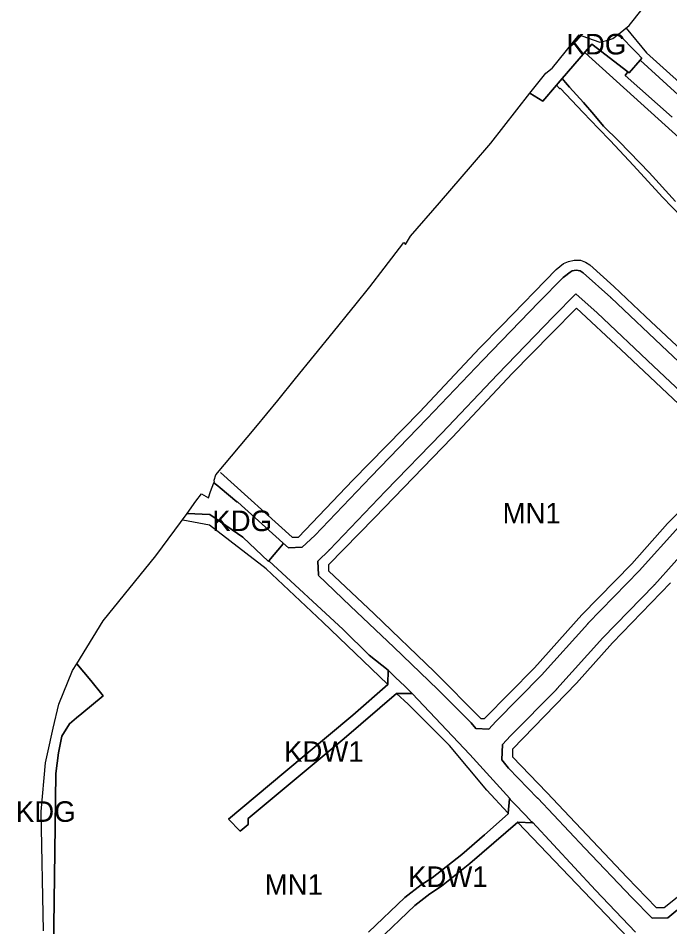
# Model space of a CAD drawing. Extents: x -284239 to -281592, y 34477 to 37267.
# Drawn here: x -284177.6 to -283861.3, y 35288.9 to 35729.6 of the extents above; entities that cross this region are included whole.
import ezdxf

# ---------------------------------------------------------------- set-up
doc = ezdxf.new("R2010")
doc.units = 0
for name, color, linetype in [('linie_rozgraniczajace', 7, 'Continuous'), ('linie_zabudowy_nieprzekraczalne', 7, 'Continuous'), ('oznaczenia_przeznaczen', 7, 'Continuous')]:
    doc.layers.add(name, color=color, linetype=linetype)

msp = doc.modelspace()

# ---------------------------------------------------------------- linework, layer by layer
at = {"layer": 'linie_rozgraniczajace'}
for points in [[(-283853.453, 35688.985), (-283875.706, 35709.29), (-283874.896, 35710.244), (-283877.331, 35712.753), (-283886.193, 35721.883), (-283881.05, 35726.03), (-283862.1, 35750)], [(-283858.476, 35640.766), (-283871.373, 35654.832), (-283875.898, 35659.508), (-283886.08, 35670.029), (-283893.471, 35677.27), (-283898.148, 35682.851), (-283903.201, 35688.734), (-283909.989, 35696.201), (-283911.984, 35698.439), (-283911.924, 35698.503), (-283913.515, 35700.413), (-283899.111, 35717.01), (-283881.66, 35703.664), (-283882.985, 35701.865), (-283860.177, 35681.585)], [(-283860.177, 35681.585), (-283882.985, 35701.865), (-283881.66, 35703.664), (-283880.949, 35703.121), (-283875.706, 35709.29), (-283853.453, 35688.985)], [(-284082.568, 35504.222), (-284082.36, 35504.76), (-284082.417, 35505.322), (-284082.44, 35505.55), (-284081.69, 35508.07), (-284062.32, 35531.2), (-284051.57, 35544.19), (-284042.96, 35554.92), (-284024.62, 35577.41), (-284015.63, 35588.44), (-284014.12, 35590.29), (-284006.97, 35599.32), (-284000, 35608.29), (-283990.33, 35620.75), (-283989.52, 35619.9), (-283987.17, 35623.85), (-283973.01, 35640.12), (-283957.01, 35658.73), (-283948.25, 35668.93), (-283929.189, 35693.195), (-283922.996, 35689.346), (-283916.301, 35697.188), (-283914.768, 35695.47), (-283914.693, 35695.567), (-283914.592, 35695.674), (-283903.352, 35683.794), (-283895.885, 35676.101), (-283890.304, 35670.256), (-283878.99, 35658.15), (-283864.887, 35642.802), (-283850.707, 35628.208)], [(-283850.707, 35628.208), (-283864.887, 35642.802), (-283878.99, 35658.15), (-283890.304, 35670.256), (-283895.885, 35676.101), (-283903.352, 35683.794), (-283914.592, 35695.674), (-283914.693, 35695.567), (-283914.768, 35695.47), (-283916.301, 35697.188), (-283915.492, 35698.136), (-283913.515, 35700.413), (-283911.924, 35698.503), (-283911.984, 35698.439), (-283909.989, 35696.201), (-283903.201, 35688.734), (-283898.148, 35682.851), (-283893.471, 35677.27), (-283886.08, 35670.029), (-283875.898, 35659.508), (-283871.373, 35654.832), (-283858.476, 35640.766)], [(-283832.706, 35540.21), (-283862.396, 35568.049), (-283889.772, 35593.97), (-283889.842, 35594.016), (-283889.881, 35594.07), (-283903.375, 35606.109), (-283904.79, 35606.997), (-283906.703, 35607.378), (-283908.617, 35606.997), (-283909.628, 35606.434), (-283912.472, 35604.383), (-283913.093, 35603.852), (-283924.877, 35591.937), (-283924.905, 35591.905), (-283952.102, 35563.785), (-283952.125, 35563.757), (-283979.168, 35535.263), (-284006.474, 35507.162), (-284033.678, 35478.771), (-284039.671, 35472.952), (-284046.408, 35472.703), (-284049.121, 35475.157), (-284070.923, 35494.887), (-284071.466, 35494.978)], [(-284055.977, 35466.345), (-284049.031, 35474.68), (-284049.121, 35475.157), (-284046.408, 35472.703), (-284039.671, 35472.952), (-284033.678, 35478.771), (-284006.474, 35507.162), (-283979.168, 35535.263), (-283952.125, 35563.757), (-283952.102, 35563.785), (-283924.905, 35591.905), (-283924.877, 35591.937), (-283913.093, 35603.852), (-283912.472, 35604.383), (-283909.628, 35606.434), (-283908.617, 35606.997), (-283906.703, 35607.378), (-283904.79, 35606.997), (-283903.375, 35606.109), (-283889.881, 35594.07), (-283889.842, 35594.016), (-283889.772, 35593.97), (-283862.396, 35568.049), (-283832.706, 35540.21)], [(-283839.578, 35532.946), (-283869.253, 35560.771), (-283896.594, 35586.658), (-283906.922, 35595.872), (-283917.747, 35584.925), (-283944.897, 35556.85), (-283971.935, 35528.358), (-283971.958, 35528.342), (-283999.282, 35500.216), (-284026.522, 35471.786), (-284026.599, 35471.733), (-284026.653, 35471.654), (-284032.194, 35466.262), (-284031.771, 35459.581), (-284031.969, 35459.4), (-284016.238, 35444.476), (-283995.189, 35424.484), (-283973.946, 35404.036), (-283973.919, 35403.997), (-283973.878, 35403.97), (-283958.003, 35388.095), (-283957.709, 35387.774), (-283955.382, 35385.003), (-283949.186, 35384.773), (-283945.821, 35388.425), (-283945.76, 35388.468), (-283945.714, 35388.537), (-283923.506, 35411.009), (-283901.161, 35435.858), (-283901.085, 35435.912), (-283901.025, 35436.004), (-283882.111, 35455.419), (-283876.156, 35461.533), (-283856.972, 35482.826)], [(-283856.972, 35482.826), (-283876.156, 35461.533), (-283882.111, 35455.419), (-283901.025, 35436.004), (-283901.085, 35435.912), (-283901.161, 35435.858), (-283923.506, 35411.009), (-283945.714, 35388.537), (-283945.76, 35388.468), (-283945.821, 35388.425), (-283949.186, 35384.773), (-283955.382, 35385.003), (-283957.709, 35387.774), (-283958.003, 35388.095), (-283973.878, 35403.97), (-283973.919, 35403.997), (-283973.946, 35404.036), (-283995.189, 35424.484), (-284016.238, 35444.476), (-284031.969, 35459.4), (-284031.771, 35459.581), (-284032.194, 35466.262), (-284026.653, 35471.654), (-284026.599, 35471.733), (-284026.522, 35471.786), (-283999.282, 35500.216), (-283971.958, 35528.342), (-283971.935, 35528.358), (-283944.897, 35556.85), (-283917.747, 35584.925), (-283906.922, 35595.872), (-283896.594, 35586.658), (-283869.253, 35560.771), (-283839.578, 35532.946)], [(-284071.466, 35494.978), (-284079.517, 35501.791), (-284080.724, 35502.812), (-284082.568, 35504.222)], [(-284160.415, 35277.536), (-284159.831, 35325.216), (-284159.284, 35363.232), (-284158.008, 35373.259), (-284156.367, 35381.282), (-284152.721, 35387.299), (-284149.248, 35390.245), (-284146.704, 35392.404), (-284136.311, 35400.973), (-284142.336, 35408.288), (-284149.101, 35416.503), (-284136.42, 35437.27), (-284110.76, 35468.87), (-284095.65, 35489.398), (-284084.642, 35488.924), (-284068.617, 35477.885), (-284056.153, 35466.133), (-284055.977, 35466.345), (-284019.886, 35433.023), (-284007.273, 35420.591), (-283997.996, 35413.307), (-283998.218, 35406.553), (-283998.214, 35406.448), (-284015.151, 35391.604), (-284048.621, 35363.558), (-284075.476, 35341.135), (-284069.92, 35335.314), (-284065.951, 35338.489), (-284065.951, 35341.399), (-284019.384, 35380.161), (-283993.969, 35402.055), (-283993.72, 35402.055), (-283986.307, 35402.055), (-283958.442, 35372.39), (-283938.982, 35351.128), (-283938.826, 35350.714), (-283939.066, 35350.961), (-283939.745, 35343.979), (-283939.815, 35343.626), (-283951.254, 35333.528), (-283962.234, 35324.003), (-283976.654, 35312.626), (-283981.946, 35309.318), (-283989.883, 35303.101), (-284007.478, 35286.3)], [(-283849.606, 35476.062), (-283868.791, 35454.767), (-283868.865, 35454.714), (-283868.924, 35454.625), (-283893.792, 35429.098), (-283916.149, 35404.235), (-283916.239, 35404.171), (-283916.31, 35404.063), (-283938.547, 35381.563), (-283942.477, 35377.365), (-283942.853, 35369.85), (-283939.609, 35365.859), (-283925.477, 35351.335), (-283925.452, 35351.296), (-283925.418, 35351.273), (-283902.612, 35327.013), (-283879.767, 35303.112), (-283869.876, 35293.092), (-283862.327, 35293.261), (-283853.715, 35300.32)], [(-283853.715, 35300.32), (-283862.327, 35293.261), (-283869.876, 35293.092), (-283879.767, 35303.112), (-283902.612, 35327.013), (-283925.418, 35351.273), (-283925.452, 35351.296), (-283925.477, 35351.335), (-283939.609, 35365.859), (-283942.853, 35369.85), (-283942.477, 35377.365), (-283938.547, 35381.563), (-283916.31, 35404.063), (-283916.239, 35404.171), (-283916.149, 35404.235), (-283893.792, 35429.098), (-283868.924, 35454.625), (-283868.865, 35454.714), (-283868.791, 35454.767), (-283849.606, 35476.062)], [(-283877.899, 35286.351), (-283897.359, 35306.712), (-283927.991, 35339.596), (-283928.372, 35339.815), (-283931.231, 35342.857), (-283932.674, 35344.392), (-283935.573, 35347.371), (-283938.826, 35350.714), (-283938.982, 35351.128), (-283958.442, 35372.39), (-283986.307, 35402.055), (-283986.883, 35402.609), (-283989.925, 35405.538), (-283994.37, 35409.817), (-283997.996, 35413.307), (-284007.273, 35420.591), (-284019.886, 35433.023), (-284055.977, 35466.345)], [(-284165.33, 35286.95), (-284166.41, 35344.78), (-284164.32, 35368.4), (-284163.38, 35372.82), (-284160.67, 35385.3), (-284157.9, 35396.8), (-284151.16, 35413.13), (-284149.101, 35416.503), (-284142.336, 35408.288), (-284136.311, 35400.973), (-284146.704, 35392.404), (-284149.248, 35390.245), (-284152.721, 35387.299), (-284156.367, 35381.282), (-284158.008, 35373.259), (-284159.284, 35363.232), (-284159.831, 35325.216), (-284160.415, 35277.536)], [(-284007.478, 35286.3), (-283989.883, 35303.101), (-283981.946, 35309.318), (-283976.654, 35312.626), (-283962.234, 35324.003), (-283951.254, 35333.528), (-283939.815, 35343.626), (-283939.745, 35343.979), (-283939.066, 35350.961), (-283938.826, 35350.714), (-283935.573, 35347.371), (-283932.674, 35344.392), (-283931.231, 35342.857), (-283928.372, 35339.815), (-283927.851, 35339.261), (-283935.03, 35339.609), (-283958.398, 35319.637), (-283972.156, 35308.525), (-283977.712, 35304.953), (-283985.121, 35299.264), (-284003.377, 35281.802)], [(-284003.377, 35281.802), (-283985.121, 35299.264), (-283977.712, 35304.953), (-283972.156, 35308.525), (-283958.398, 35319.637), (-283935.03, 35339.609), (-283927.851, 35339.261), (-283928.372, 35339.815), (-283927.991, 35339.596), (-283897.359, 35306.712), (-283877.899, 35286.351)]]:
    msp.add_lwpolyline(points, dxfattribs=at)
for points in [[(-283929.189, 35693.195), (-283921.55, 35702.92), (-283918.34, 35705.44), (-283918.286, 35705.508), (-283905.34, 35721.57), (-283901.246, 35720.113), (-283895.34, 35718.01), (-283892.081, 35718.849), (-283890.87, 35719.16), (-283890.375, 35719.296), (-283888.9, 35719.7), (-283886.193, 35721.883), (-283877.331, 35712.753), (-283874.896, 35710.244), (-283875.706, 35709.29), (-283880.949, 35703.121), (-283881.66, 35703.664), (-283899.111, 35717.01), (-283913.515, 35700.413), (-283915.492, 35698.136), (-283916.301, 35697.188), (-283922.996, 35689.346)], [(-284095.65, 35489.398), (-284091.32, 35495.28), (-284088.67, 35498.97), (-284085.16, 35496.95), (-284084.2, 35500), (-284082.568, 35504.222), (-284080.724, 35502.812), (-284079.517, 35501.791), (-284071.466, 35494.978), (-284070.923, 35494.887), (-284049.121, 35475.157), (-284049.031, 35474.68), (-284055.977, 35466.345), (-284056.153, 35466.133), (-284068.617, 35477.885), (-284084.642, 35488.924)], [(-284075.476, 35341.135), (-284048.621, 35363.558), (-284015.151, 35391.604), (-283998.214, 35406.448), (-283998.218, 35406.553), (-283997.996, 35413.307), (-283994.37, 35409.817), (-283989.925, 35405.538), (-283986.883, 35402.609), (-283986.307, 35402.055), (-283993.72, 35402.055), (-283993.969, 35402.055), (-284019.384, 35380.161), (-284065.951, 35341.399), (-284065.951, 35338.489), (-284069.92, 35335.314)]]:
    msp.add_lwpolyline(points, close=True, dxfattribs=at)
at = {"layer": 'linie_zabudowy_nieprzekraczalne'}
for points in [[(-283882.491, 35724.719), (-283872.569, 35712.813), (-283846.845, 35689.694), (-283801.999, 35649.411), (-283772.233, 35621.762), (-283745.642, 35598.28), (-283701.324, 35558.064), (-283677.512, 35537.294), (-283659.652, 35520.691), (-283649.466, 35512.886), (-283605.677, 35520.427)], [(-283674.337, 35504.75), (-283673.808, 35506.337), (-283690.08, 35521.419), (-283711.511, 35540.138), (-283735.059, 35561.834), (-283755.564, 35580.156), (-283781.89, 35603.572), (-283810.862, 35630.097), (-283851.74, 35667.138), (-283902.41, 35712.781)], [(-284079.344, 35509.278), (-284044.622, 35477.829), (-284041.579, 35477.829), (-284015.121, 35505.544), (-283982.709, 35538.683), (-283953.737, 35569.507), (-283942.757, 35580.553), (-283916.431, 35607.673), (-283912.859, 35610.583), (-283910.478, 35611.642), (-283907.7, 35612.303), (-283904.657, 35612.171), (-283902.276, 35611.245), (-283900.159, 35609.988), (-283888.385, 35599.405), (-283873.172, 35584.985), (-283829.912, 35544.437)], [(-283830.706, 35517.45), (-283851.211, 35537.095), (-283885.078, 35568.845), (-283906.641, 35588.954), (-283918.68, 35576.717), (-283937.598, 35557.402), (-283966.967, 35526.247), (-284004.67, 35487.287), (-284027.027, 35464.401), (-284026.895, 35461.623), (-284004.802, 35440.654), (-283975.566, 35412.609), (-283952.944, 35389.987), (-283951.224, 35389.987), (-283927.014, 35414.527), (-283903.996, 35440.258), (-283879.786, 35464.996), (-283862.456, 35484.443), (-283849.491, 35497.606), (-283835.998, 35511.761), (-283830.97, 35517.318)], [(-283998.329, 35406.625), (-284029.673, 35436.62), (-284057.19, 35462.549), (-284084.766, 35483.683), (-284097.73, 35486.065)], [(-283861.001, 35455.67), (-283889.179, 35426.565), (-283906.641, 35407.052), (-283937.598, 35375.038), (-283937.598, 35371.333), (-283921.061, 35354.069), (-283882.035, 35312.86), (-283867.88, 35298.176), (-283864.043, 35298.308), (-283834.542, 35321.724)], [(-283939.856, 35344.184), (-283950.033, 35355.128), (-283968.157, 35376.824), (-283988.266, 35396.932), (-283993.964, 35401.995)], [(-283990.921, 35187.021), (-283984.165, 35194.724), (-283971.994, 35205.969), (-283966.57, 35210.202), (-283950.959, 35223.563), (-283930.454, 35240.828), (-283881.638, 35283.624), (-283935.094, 35339.421)]]:
    msp.add_lwpolyline(points, dxfattribs=at)

# ---------------------------------------------------------------- texts
at = {"layer": 'oznaczenia_przeznaczen'}
for s, p in [('KDG', (-283911.411, 35712.01)), ('MN1', (-283942.471, 35484.524)), ('KDG', (-284083.363, 35480.817)), ('KDW1', (-284048.536, 35368.911)), ('KDG', (-284178.71, 35339.78)), ('KDW1', (-283988.337, 35308.179)), ('MN1', (-284057.945, 35304.409))]:
    msp.add_text(s, height=10, dxfattribs=at).set_placement(p)

doc.saveas('drawing.dxf')
